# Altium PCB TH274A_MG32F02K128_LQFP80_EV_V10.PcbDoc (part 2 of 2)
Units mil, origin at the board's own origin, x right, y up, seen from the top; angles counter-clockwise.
Board outline 4251.97 x 2637.8 mil, 2 copper layers (Top Layer, Bottom Layer); 159 components, 159 nets, 691 pads, 305 vias.
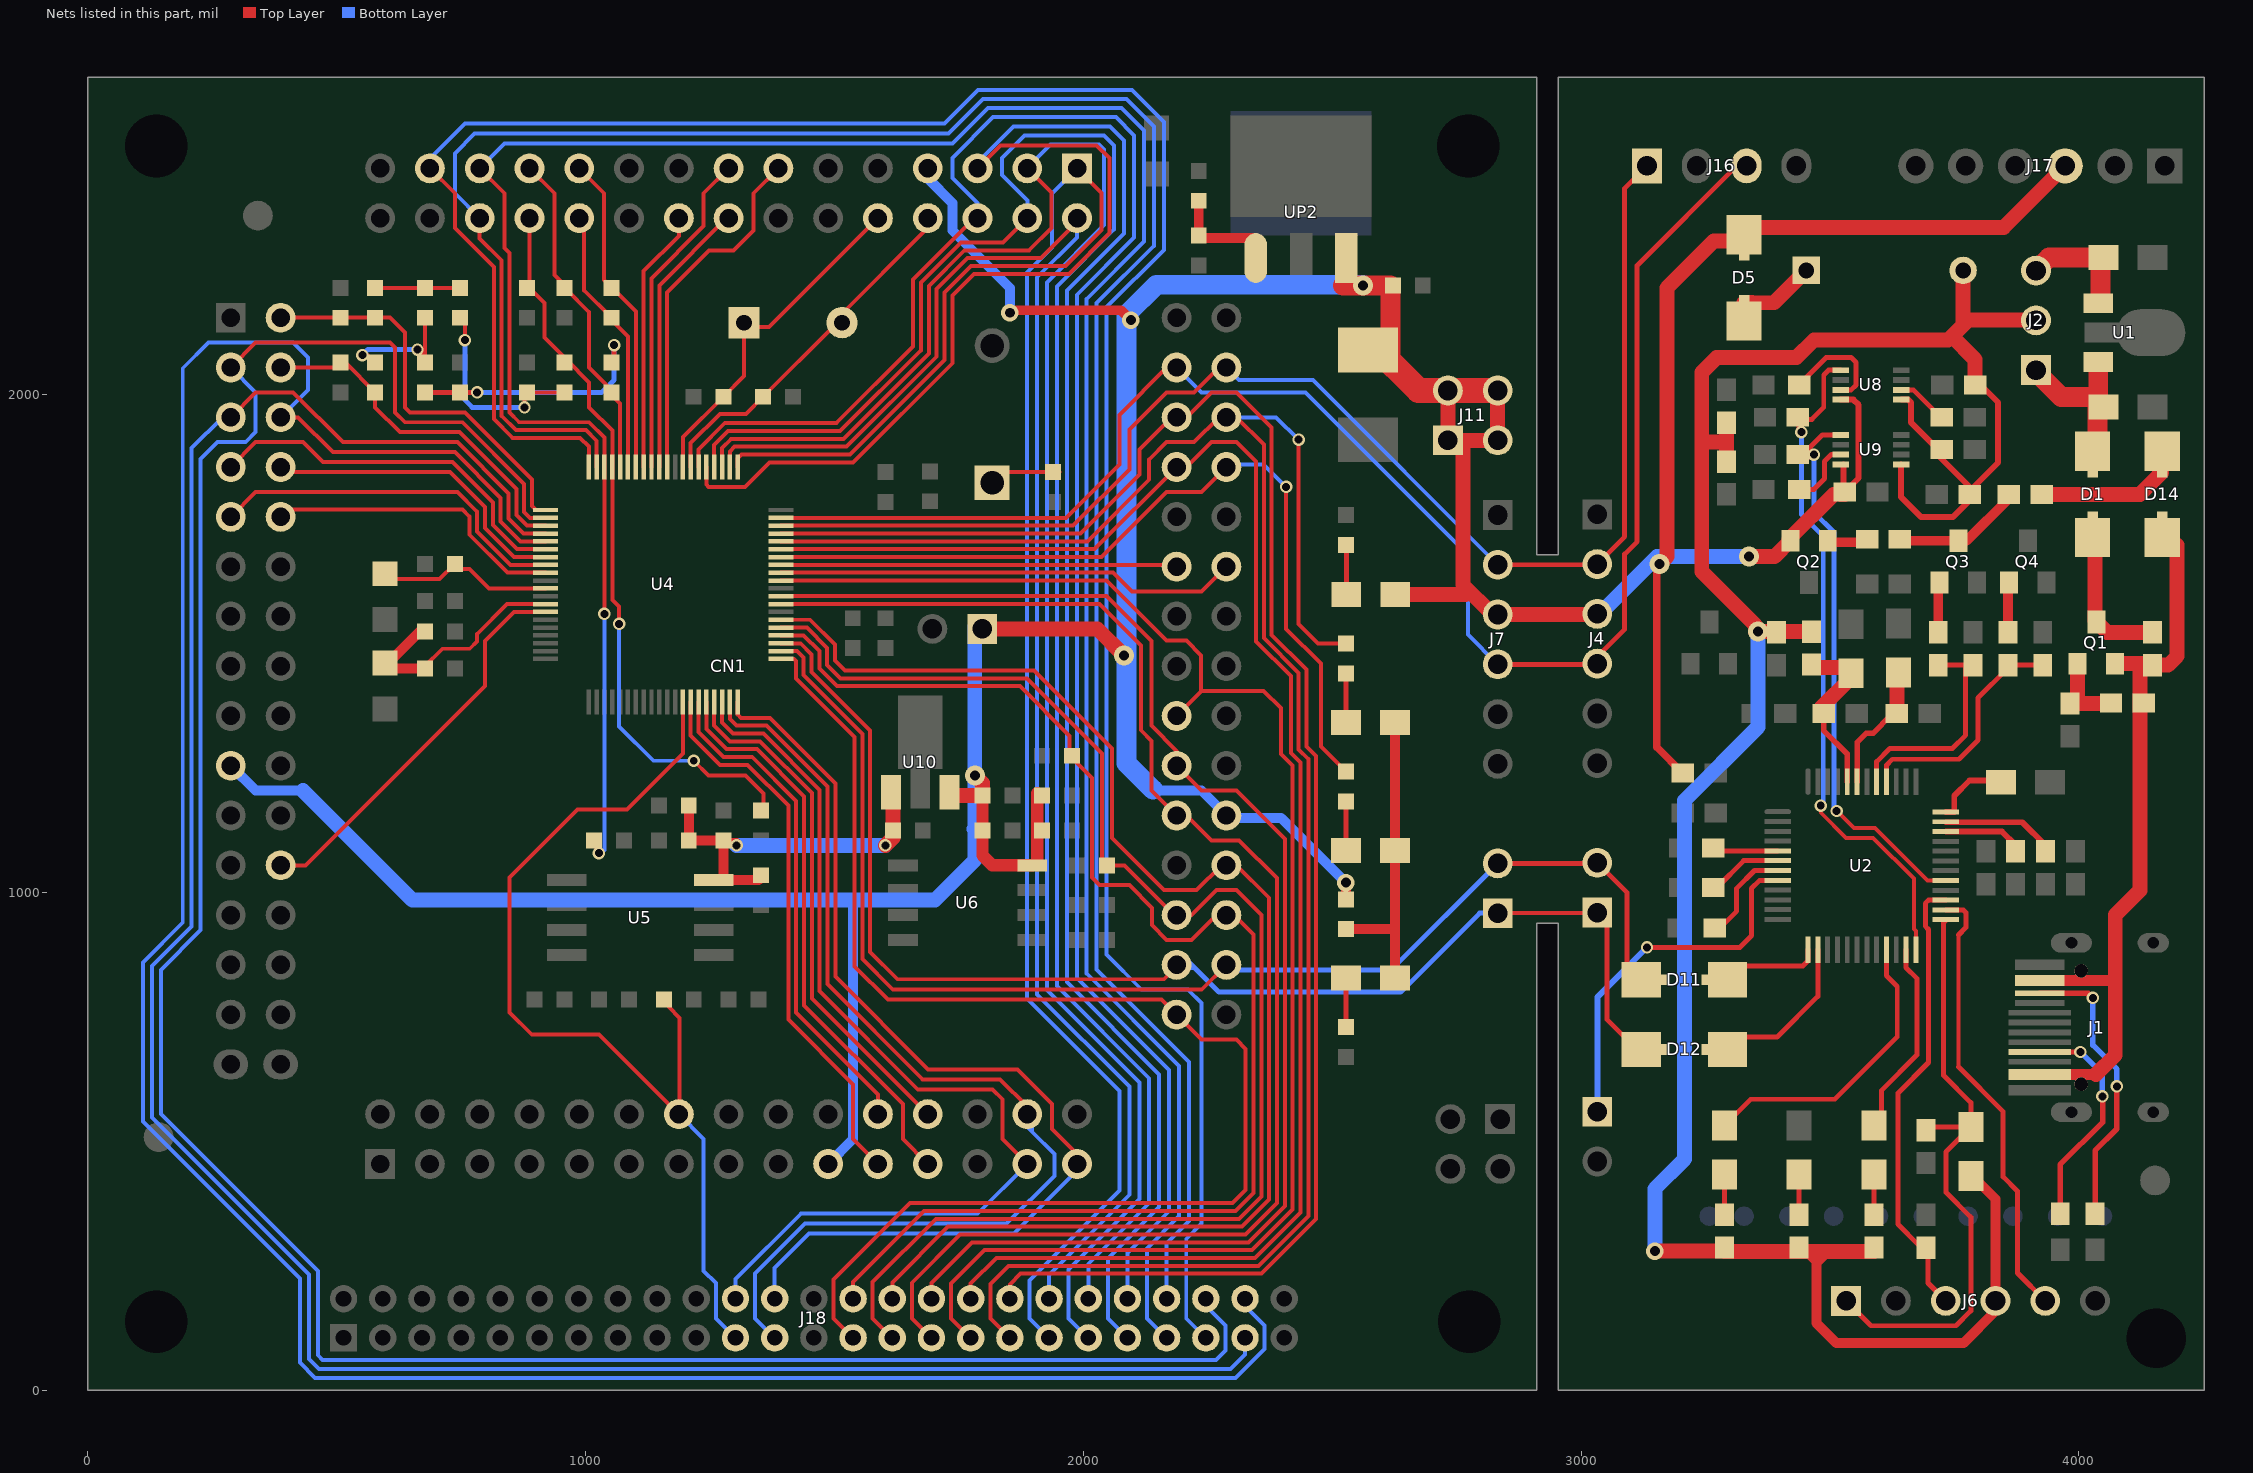
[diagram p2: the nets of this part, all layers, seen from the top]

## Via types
v1: diameter 20, hole 12, Top Layer to Bottom Layer, tented both sides, 214 vias
v2: diameter 25, hole 16, Top Layer to Bottom Layer, tented both sides, 55 vias
v3: diameter 30, hole 12, Top Layer to Bottom Layer, tented both sides, 13 vias
v4: diameter 40, hole 20, Top Layer to Bottom Layer, tented both sides, 7 vias
v5: diameter 25, hole 12, Top Layer to Bottom Layer, tented both sides, 6 vias
v6: diameter 35, hole 20, Top Layer to Bottom Layer, tented both sides, 6 vias
v7: diameter 30, hole 16, Top Layer to Bottom Layer, tented both sides, 2 vias
v8: diameter 15, hole 12, Top Layer to Bottom Layer, tented both sides, 1 vias
v9: diameter 28, hole 16, Top Layer to Bottom Layer, tented both sides, 1 vias

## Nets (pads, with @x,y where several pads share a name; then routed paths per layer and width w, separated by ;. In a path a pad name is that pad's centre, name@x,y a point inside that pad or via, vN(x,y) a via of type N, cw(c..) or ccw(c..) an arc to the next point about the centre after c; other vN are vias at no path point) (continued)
LCD_P18: CN1.14 J18.21 R50.1 U4.13 | length 1979.7
  Top Layer w8: R50.1@1167.48,785 1167.48,770 1189.12,748.36 CN1.14@1189.12,556.64 ; CN1.14@1184.2,558.28 1027.48,715 892.04,715 847.48,759.56 847.48,1030.71 984.03,1167.26 1083.44,1167.26 1195.59,1279.41 U4.13@1195.59,1382.91
  Bottom Layer w8: CN1.14@1187.48,555 1237.48,505 1237.48,240 1261.97,215.51 1261.97,145 J18.21@1301.34,105.63
LCD_P19: CN1.27 J18.22 U4.18 | length 2013.1
  Top Layer w8: U4.18@1274.33,1382.91 1274.33,1342.1 1296.67,1319.76 1357.26,1319.76 1470.47,1206.55 1470.47,802.01 1667.48,605 1817.48,605 1837.48,585 1837.48,505 CN1.27@1877.92,464.56
  Bottom Layer w8: J18.22@1301.34,184.37 1301.34,223.86 1432.48,355 1787.48,355 CN1.27@1887.48,455
LCD_P20: CN1.28 J18.23 U4.19 | length 2176.1
  Top Layer w8: U4.19@1290.08,1382.91 1290.08,1348.62 1303.19,1335.51 1363.78,1335.51 1486.22,1213.07 1486.22,816.26 1677.48,625 1832.48,625 1887.48,570 CN1.28@1887.48,555
  Bottom Layer w8: J18.23@1380.08,105.63 1340.71,145 1340.71,234.94 1440.76,335 1845.67,335 1941.93,431.26 1941.93,475 1897.48,519.45 ; CN1.28@1887.48,529.45 1897.48,519.45 ; CN1.28@1897.48,545 1897.48,519.45
LCD_P21: CN1.29 J18.24 U4.20 | length 2093.6
  Top Layer w8: U4.20@1305.83,1382.91 1305.83,1357.87 1312.44,1351.26 1370.3,1351.26 1501.97,1219.6 1501.97,831.22 1688.19,645 1867.99,645 1937.48,575.51 1937.48,525 CN1.29@1987.48,475 ; CN1.29@1987.48,454.29 CN1.29@1987.48,455
  Bottom Layer w8: J18.24@1380.08,184.37 1380.08,246.16 1448.91,315 1860.67,315 1987.48,441.81 CN1.29@1987.48,455
LCD_P22: CN1.32 J18.27 U4.21 | length 2867.9
  Top Layer w8: U4.21@1392.44,1469.53 1418.66,1469.53 1422.48,1465.71 1422.48,1430.46 1540.43,1312.51 1540.43,852.05 1607.48,785 2157.48,785 CN1.32@2187.48,755 2237.48,705 2307.48,705 2326.18,686.3 2326.18,402.88 2299.56,376.26 1651.93,376.26 1498.19,222.52 1498.19,145 J18.27@1537.56,105.63
LCD_P23: CN1.35 J18.28 R47.1 U4.24 | length 2862.9
  Top Layer w8: U4.24@1392.44,1516.77 1438.23,1516.77 1469.72,1485.28 1469.72,1450.48 1505.45,1414.76 1872.72,1414.76 1972.68,1314.8 R47.1@1972.68,1275 ; J18.28@1537.56,184.37 1537.56,218.23 1679.84,360.51 2306.08,360.51 2341.93,396.36 2341.93,916.3 2303.23,955 CN1.35@2287.48,955 2267.48,955 2217.48,905 2167.48,905 2137.89,934.59 2137.89,969.59 2092.48,1015 2032.48,1015 2017.48,1030 2017.48,1230.2 1975.08,1272.6 R47.1@1972.68,1275 ; R47.1@1972.68,1284.8 R47.1@1972.68,1275
LCD_P24: CN1.36 J18.29 R46.1 U4.25 | length 2938.9
  Top Layer w8: U4.25@1392.44,1532.52 1444.75,1532.52 1485.47,1491.8 1485.47,1457.01 1511.97,1430.51 1886.97,1430.51 2037.48,1280 2037.48,1055 R46.1@2047.48,1055 ; J18.29@1616.3,105.63 1576.93,145 1576.93,217.6 1704.09,344.76 2312.61,344.76 2357.68,389.83 2357.68,955.51 2308.19,1005 2267.48,1005 2217.48,955 CN1.36@2187.48,955 2182.48,955 2082.48,1055 R46.1@2052.48,1055
LCD_P25: CN1.37 J18.30 U4.26 | length 2842.7
  Top Layer w8: U4.26@1392.44,1548.27 1451.28,1548.27 1501.22,1498.32 1501.22,1466.26 1521.22,1446.26 1900.71,1446.26 2057.48,1289.49 2057.48,1110 2162.48,1005 2227.48,1005 2277.48,1055 CN1.37@2287.48,1055 2308.19,1055 2373.42,989.76 2373.42,383.31 2319.13,329.02 1728.35,329.02 1616.3,216.97 J18.30@1616.3,184.37
LCD_P26: CN1.40 J18.31 U4.28 | length 2962.2
  Top Layer w8: U4.28@1392.44,1579.76 2032.72,1579.76 2115.72,1496.76 2115.72,1326.25 2136.97,1305 2136.97,1205.51 CN1.40@2187.48,1155 2207.48,1155 2257.48,1105 2313.19,1105 2389.17,1029.02 2389.17,376.79 2325.65,313.27 1752.6,313.27 1655.67,216.34 1655.67,145 J18.31@1695.04,105.63
LCD_P27: CN1.42 J18.32 U4.29 | length 2874.7
  Top Layer w8: U4.29@1392.44,1595.51 2046.97,1595.51 2136.93,1505.55 2136.93,1335.55 2187.48,1285 CN1.42@2187.48,1255 2237.48,1205 2308.19,1205 2404.92,1108.27 2404.92,370.27 2332.17,297.52 1776.85,297.52 1695.04,215.71 J18.32@1695.04,184.37
LCD_P28: CN1.44 J18.33 U4.31 | length 3113.4
  Top Layer w8: U4.31@1392.44,1627.01 2046.18,1627.01 2166.93,1506.26 2206.93,1506.26 2236.93,1476.26 2236.93,1404.45 ; J18.33@1773.78,105.63 1734.41,145 1734.41,215.08 1801.1,281.77 2338.7,281.77 2420.67,363.74 2420.67,1255 2396.93,1278.74 2396.93,1370.55 2362.48,1405 2237.48,1405 2236.93,1404.45 ; CN1.44@2187.48,1355 2236.93,1404.45
LCD_P29: CN1.54 J18.34 U4.35 | length 3357.6
  Top Layer w8: U4.35@1392.44,1690 2022.48,1690 2184.98,1852.5 2187.48,1852.5 2189.98,1852.5 2192.48,1855 2207.48,1855 2257.48,1905 2308.19,1905 2346.93,1866.26 2346.93,1504.92 2416.93,1434.92 2416.93,1281.01 2436.42,1261.52 2436.42,357.22 2345.22,266.02 1825.35,266.02 1773.78,214.45 J18.34@1773.78,184.37
LCD_P30: CN1.55 J18.35 R55.1 U4.36 | length 4213.6
  Top Layer w8: U4.36@1392.44,1705.75 2008.23,1705.75 2132.48,1830 2132.48,1870 2167.48,1905 2222.48,1905 2272.48,1955 CN1.55@2287.48,1955 2308.19,1955 2362.68,1900.51 2362.68,1511.44 2432.68,1441.44 2432.68,1335 2432.68,1287.53 2452.17,1268.04 2452.17,350.7 2351.74,250.28 1849.61,250.28 1813.15,213.82 1813.15,145 J18.35@1852.52,105.63 ; v2(2432.48,1910) 2432.48,1539.49 2471.65,1500.32 R55.1@2527.52,1500.32 2485.94,1500.32
  Bottom Layer w8: CN1.55@2287.48,1955 2387.48,1955 v2(2432.48,1910)
LCD_P31: CN1.56 J18.36 U4.37 | length 3487.9
  Top Layer w8: U4.37@1392.44,1721.5 1993.98,1721.5 2112.48,1840 2112.48,1890 2177.48,1955 CN1.56@2187.48,1955 2207.28,1955 2257.28,2005 2308.19,2005 2378.42,1934.76 2378.42,1517.96 2448.42,1447.97 2448.42,1294.06 2467.91,1274.57 2467.91,344.17 2358.27,234.53 1873.86,234.53 1852.52,213.19 J18.36@1852.52,184.37
LCD_P32: CN1.61 J18.37 U4.41 | length 3720.9
  Top Layer w8: U4.41@1305.83,1855.35 1305.83,1872.16 1313.77,1880.1 1531.23,1880.1 1721.18,2070.05 1721.18,2205.97 1774.22,2259.02 1964.68,2259.02 2036.93,2331.26 2036.93,2405.55 CN1.61@1987.48,2455
  Bottom Layer w8: J18.37@1931.26,105.63 1891.89,145 1891.89,220.83 2072.48,401.42 2072.48,602.01 1886.93,787.56 1886.93,2246.26 1936.93,2296.26 1936.93,2404.45 CN1.61@1987.48,2455
LCD_P33: CN1.62 J18.38 U4.42 | length 3352.1
  Top Layer w8: U4.42@1290.08,1855.35 1290.08,1886.63 1299.3,1895.85 1524.71,1895.85 1705.43,2076.58 1705.43,2212.49 1767.7,2274.76 1915.43,2274.76 CN1.62@1991.57,2350.91
  Bottom Layer w8: J18.38@1931.26,184.37 1931.26,231.92 2092.48,393.14 2092.48,610.29 1906.93,795.85 1906.93,2236.26 1986.93,2316.26 CN1.62@1986.93,2355
LCD_P34: CN1.63 J18.39 U4.43 | length 3866.6
  Top Layer w8: U4.43@1274.33,1855.35 1274.33,1893.15 1292.78,1911.6 1518.18,1911.6 1689.68,2083.1 1689.68,2219.02 1761.18,2290.51 1891.18,2290.51 1935.93,2335.26 1935.93,2406.55 CN1.63@1887.48,2455
  Bottom Layer w8: CN1.63@1887.48,2456.74 1933.74,2503 2031.93,2503 2041.93,2493 2041.93,2340.97 1926.93,2225.97 1926.93,804.13 2112.48,618.58 2112.48,384.85 1970.63,243 1970.63,145 J18.39@2010,105.63
LCD_P35: CN1.64 J18.40 U4.44 | length 3840.9
  Top Layer w8: U4.44@1258.58,1855.35 1258.58,1899.67 1286.26,1927.35 1511.66,1927.35 1673.94,2089.62 1673.94,2225.54 1754.66,2306.26 1838.74,2306.26 CN1.64@1887.48,2355
  Bottom Layer w8: CN1.64@1887.48,2341.81 CN1.64@1887.48,2355 1887.48,2390.71 1836.93,2441.26 1836.93,2476.26 1881.93,2521.26 2041.93,2521.26 2061.93,2501.26 2061.93,2332.68 1946.93,2217.68 1946.93,812.41 2132.48,626.86 2132.48,376.57 2010,254.09 J18.40@2010,184.37
LCD_P36: CN1.65 J18.41 U4.45 | length 4586.3
  Top Layer w8: U4.45@1242.83,1855.35 1242.83,1819.65 1247.48,1815 1320.67,1815 1370.02,1864.36 1537.75,1864.36 1736.93,2063.53 1736.93,2199.45 1780.75,2243.27 1971.21,2243.27 2052.68,2324.74 2052.68,2475.55 2026.97,2501.26 1916.93,2501.26 ; CN1.65@1787.48,2455 1833.74,2501.26 1916.93,2501.26 ; 1851.93,2501.26 1916.93,2501.26
  Bottom Layer w8: CN1.65@1787.48,2455 1787.48,2466.81 1860.19,2539.52 2053.67,2539.52 2081.93,2511.26 2081.93,2324.4 1966.93,2209.4 1966.93,820.7 2152.48,635.15 2152.48,368.28 2049.37,265.17 2049.37,145 J18.41@2088.74,105.63
LCD_P37: CN1.66 J18.42 U4.46 | length 3918.9
  Top Layer w8: U4.46@1227.09,1855.35 1227.09,1890.45 1279.73,1943.1 1503.76,1943.1 1657.68,2097.01 1657.68,2231.55 1781.12,2355 CN1.66@1787.48,2355
  Bottom Layer w8: CN1.66@1787.48,2355 1787.48,2385 1736.93,2435.55 1736.93,2476.26 1818.45,2557.78 2065.41,2557.78 2101.93,2521.26 2101.93,2316.11 1986.93,2201.11 1986.93,828.98 2172.48,643.43 2172.48,360 2088.74,276.26 J18.42@2088.74,184.37
LCD_P38: CN1.85 J18.43 R53.1 U4.58 | length 5585.5
  Top Layer w8: CN1.85@787.48,2455 837.48,2405 837.48,2295 847.48,2285 847.48,1964.41 866.89,1945 1007.48,1945 1038.11,1914.37 U4.58@1038.11,1855.35 v2(1038.11,1560) ; v2@1021.97,1079.41 R53.1@1021.97,1104.41
  Bottom Layer w8: CN1.85@787.48,2455 837.48,2505 1737.48,2505 1808.52,2576.04 2077.15,2576.04 2121.93,2531.26 2121.93,2307.83 2006.93,2192.83 2006.93,837.27 2192.48,651.72 2192.48,350 2128.11,285.63 2128.11,145 J18.43@2167.48,105.63 ; v2@1031.97,1079.41 1038.11,1085.55 v2(1038.11,1560)
  other v2: 1026.97,1079.41
LCD_P39: CN1.86 J18.44 U4.59 | length 4930.7
  Top Layer w8: CN1.86@787.48,2355 787.48,2314.25 831.73,2270 831.73,1957.88 860.36,1929.25 1000.96,1929.25 1022.36,1907.85 U4.59@1022.36,1855.35
  Bottom Layer w8: CN1.86@787.48,2355 737.48,2405 737.48,2485 777.48,2525 947.48,2525 ; 817.48,2525 947.48,2525 ; J18.44@2167.48,184.37 2167.48,295 2212.48,340 2212.48,660 2026.93,845.55 2026.93,2184.54 2141.93,2299.54 2141.93,2539.54 2087.17,2594.3 1798.49,2594.3 1729.2,2525 947.48,2525
LCD_P40: CN1.87 J18.45 U4.60 | length 5071.3
  Top Layer w8: CN1.87@687.48,2455 737.48,2405 737.48,2335 815.98,2256.5 815.98,1951.36 853.84,1913.5 988.98,1913.5 1006.61,1895.87 U4.60@1006.61,1855.35
  Bottom Layer w8: CN1.87@687.48,2455 687.48,2475 757.48,2545 827.48,2545 ; 817.48,2545 827.48,2545 ; J18.45@2232.48,119.37 J18.45@2246.22,105.63 2206.85,145 2206.85,304.43 2237.42,335 2237.42,778 2210.42,805 2117.42,805 2046.93,875.49 2046.93,2176.26 2161.93,2291.26 2161.93,2548.61 2097.98,2612.56 1788.47,2612.56 1720.91,2545 827.48,2545
LCD_P41: CN1.93 J18.46 U4.62 | length 5097
  Top Layer w8: CN1.93@287.48,2055 337.48,2105 607.48,2105 617.48,2095 617.48,1965 637.48,1945 752.48,1945 876.73,1820.75 876.73,1764.99 888.73,1752.99 U4.62@920,1752.99
  Bottom Layer w8: CN1.93@287.48,2055 337.48,2005 337.48,1925 317.48,1905 260.67,1905 226.93,1871.26 226.93,924.96 146.93,844.96 146.93,555.55 462.48,240 462.48,70.71 471.93,61.26 2266.93,61.26 2285.59,79.92 2285.59,130.72 J18.46@2246.22,170.09
LCD_P42: CN1.95 J18.47 U4.64 | length 4832.2
  Top Layer w8: CN1.95@287.48,1955 337.48,2005 412.48,2005 512.48,1905 742.48,1905 845.24,1802.24 845.24,1751.94 875.68,1721.5 U4.64@920,1721.5
  Bottom Layer w8: CN1.95@287.48,1955 270.67,1955 208.93,1893.26 208.93,932.42 128.93,852.42 128.93,548.1 444.48,232.54 444.48,63.25 464.47,43.26 2295.87,43.26 2324.96,72.35 J18.47@2324.96,105.63
LCD_P43: CN1.96 J18.48 U4.65 | length 5330.8
  Top Layer w8: CN1.96@387.48,1955 422.48,1955 492.48,1885 737.48,1885 829.49,1792.99 829.49,1745.42 869.16,1705.75 U4.65@920,1705.75
  Bottom Layer w8: CN1.96@387.48,1955 442.48,2010 442.48,2075 412.48,2105 242.48,2105 190.93,2053.45 190.93,939.87 110.93,859.87 110.93,540.64 426.48,225.09 426.48,55.8 457.02,25.26 2306.16,25.26 2364.33,83.43 2364.33,130.72 J18.48@2324.96,170.09
LCD_V1: R80.1 R81.2 R100.2 | length 396.2
  Top Layer w8: v2(757.48,2110) R80.1@757.48,2150 ; v2(877.48,1975) R81.2@877.48,2000 ; R81.2@882.48,2005 R100.2@957.48,2005 R100.2@967.48,2005
  Bottom Layer w10: v2(757.48,2110) 757.48,1990 772.48,1975 v2(877.48,1975)
LCD_V2: R79.1 R80.2 R99.2 | length 180
  Top Layer w8: R99.2@577.48,2215 R79.1@677.48,2215 R80.2@747.48,2215 R80.2@757.48,2215
LCD_V3: R78.1 R79.2 R98.2 | length 258.2
  Top Layer w8: v2(551.89,2080) 562.48,2080 R98.2@577.48,2065 ; v2(662.48,2091) R78.1@677.48,2076 ; R78.1@677.48,2065 R78.1@677.48,2076 ; R79.2@677.48,2155 677.48,2091 R78.1@677.48,2076
  Bottom Layer w10: v2(551.89,2080) 562.89,2091 v2(662.48,2091)
LCD_VT: R33.1 R78.2 R97.2 | length 497.4
  Top Layer w10: R78.2@677.48,2005 R33.1@747.48,2005 v2(782.48,2005) ; R97.2@1052.48,2065 1057.48,2070 v2(1057.48,2100)
  Bottom Layer w10: v2(782.48,2005) 1032.48,2005 1057.48,2030 v2(1057.48,2100)
MG_PA0: CN1.114 U4.74 | length 796.3
  Top Layer w8: CN1.114@387.48,1055 437.55,1055 797.95,1415.4 797.95,1505.86 856.11,1564.02 U4.74@920,1564.02
MG_PB8(TX): CN1.33 D11.2 J5.2 J15.2 U4.22 | length 2596.8
  Top Layer w8: U4.22@1392.44,1485.28 1425.18,1485.28 1438.23,1472.23 1438.23,1436.98 1556.18,1319.03 1556.18,866.3 1617.48,805 2237.48,805 CN1.33@2287.48,855
  Top Layer w10: J15.2@2832.52,1058.74 J5.2@3032.52,1058.74 ; J5.2@3032.52,1060 3092.52,1000 3092.52,825 D11.2@3092.52,810
  Bottom Layer w10: CN1.33@2282.52,845 2287.48,845 2618.78,845 J15.2@2832.52,1058.74
MG_PB9(RX): CN1.34 D12.1 J5.1 J15.1 U4.23 | length 2593.9
  Top Layer w8: U4.23@1392.44,1501.02 1431.71,1501.02 1453.98,1478.75 1453.98,1443.5 1571.93,1325.55 1571.93,880.55 1626.41,826.07 2161.74,826.07 CN1.34@2187.48,851.81 ; J15.1@2832.52,958.74 J5.1@3032.52,958.74 ; J5.1@3032.52,960 J5.1@3038.29,954.23
  Top Layer w10: J5.1@3052.52,958 3052.52,745 D12.1@3105.91,691.61
  Bottom Layer w10: CN1.34@2202.48,850 2222.48,850 ; CN1.34@2212.48,860 2222.48,850 ; J15.1@2832.52,958.74 2796.22,958.74 2637.48,800 2272.48,800 2222.48,850
MG_PC0: CN1.53 R54.1 U4.34 | length 1729.8
  Top Layer w8: U4.34@1392.44,1674.25 2036.73,1674.25 2167.48,1805 2237.48,1805 CN1.53@2287.48,1855 ; v2(2407.48,1815) 2407.48,1530 2477.48,1460 2477.48,1293.5 R54.1@2527.52,1243.46
  Bottom Layer w8: CN1.53@2287.48,1860 2362.48,1860 v2(2407.48,1815)
MG_PD0: C66.1 CN1.81 U4.54 | length 646.7
  Top Layer w8: CN1.81@987.48,2455 1037.48,2405 1037.48,2231.22 1053.09,2215.61 1101.1,2167.6 U4.54@1101.1,1855.35
MG_PD1: C66.2 CN1.82 U4.55 | length 540.2
  Top Layer w8: CN1.82@987.48,2355 997.48,2345 997.48,2210 1049.98,2157.5 1049.98,2155 1049.98,2152.5 1085.35,2117.13 U4.55@1085.35,1855.35
MG_PD2: C62.1 CN1.83 R97.1 U4.56 | length 675.1
  Top Layer w8: CN1.83@887.48,2455 937.48,2405 937.48,2241 960.48,2218 960.48,2215 960.48,2213 1007.48,2166 1007.48,2055 1047.48,2015 1047.48,2005 1049.98,2002.5 1069.61,1982.87 U4.56@1069.61,1855.35
MG_PD3: C65.1 CN1.84 R51.1 R100.1 U4.57 | length 1528.9
  Top Layer w8: C65.1@884.98,2217.5 C65.1@887.48,2215 ; 887.48,2305 CN1.84@887.48,2355 C65.1@887.48,2215 ; v2(1067.48,1540) 1067.48,1574.49 1053.86,1588.11 U4.57@1053.86,1855.35 1053.86,1928.62 1007.48,1975 1007.48,2025 962.48,2070 917.48,2115 917.48,2185 C65.1@887.48,2215 ; v2(1217.48,1265) 1247.48,1235 1321.56,1235 1357.48,1199.08 R51.1@1357.48,1165
  Bottom Layer w8: v2(1067.48,1540) 1067.48,1334.2 1136.68,1265 v2(1217.48,1265)
MG_PD7: C64.1 CN1.92 R99.1 U4.61 | length 811.4
  Top Layer w8: CN1.92@387.48,2155 C64.1@507.48,2155 R99.1@577.48,2155 607.48,2155 637.48,2125 637.48,1975 647.48,1965 757.48,1965 892.48,1830 892.48,1776.97 900.71,1768.74 U4.61@920,1768.74
MG_PD9: C63.1 CN1.94 R98.1 U4.63 | length 726.8
  Top Layer w8: CN1.94@387.48,2055 507.48,2055 527.48,2055 ; C63.1@517.48,2065 R98.1@577.48,2005 577.48,1975 627.48,1925 747.33,1925 860.98,1811.34 860.98,1758.46 882.2,1737.24 U4.63@920,1737.24
MG_PD12: CN1.97 U4.66 | length 768.6
  Top Layer w8: CN1.97@287.48,1855 337.48,1905 432.48,1905 472.48,1865 732.48,1865 813.74,1783.74 813.74,1738.9 862.64,1690 U4.66@920,1690
MG_PD13: CN1.98 U4.67 | length 632.1
  Top Layer w8: CN1.98@387.48,1855 397.48,1845 727.48,1845 797.99,1774.49 797.99,1732.37 856.11,1674.25 U4.67@920,1674.25
MG_PD14: CN1.99 U4.68 | length 737
  Top Layer w8: CN1.99@287.48,1755 337.48,1805 742.48,1805 782.24,1765.24 782.24,1725.85 849.59,1658.5 U4.68@920,1658.5
MG_PD15: CN1.100 U4.69 | length 608.8
  Top Layer w8: CN1.100@387.48,1765 392.48,1770 752.48,1770 766.5,1755.98 766.5,1719.33 843.07,1642.76 U4.69@920,1642.76
MG_PE0: CN1.21 U4.14 | length 1116
  Top Layer w8: U4.14@1211.34,1382.91 1211.34,1316.01 1270.57,1256.77 1325.71,1256.77 1407.48,1175 1407.48,745 1537.44,615.04 1537.44,505.04 CN1.21@1587.48,455
MG_PE1: CN1.22 U4.15 | length 1011.1
  Top Layer w8: U4.15@1227.09,1382.91 1227.09,1322.53 1277.1,1272.52 1334.96,1272.52 1423.23,1184.25 1423.23,759.25 1587.48,595 CN1.22@1587.48,555
MG_PE2: CN1.23 U4.16 | length 1147.6
  Top Layer w8: U4.16@1242.83,1382.91 1242.83,1329.05 1283.62,1288.27 1344.21,1288.27 1438.98,1193.5 1438.98,773.5 1637.44,575.04 1637.44,505.04 CN1.23@1687.48,455
MG_PE3: CN1.24 U4.17 | length 1041.1
  Top Layer w8: U4.17@1258.58,1382.91 1258.58,1335.58 1290.14,1304.02 1350.74,1304.02 1454.72,1200.03 1454.72,787.76 CN1.24@1687.48,555
MG_PE8: CN1.49 U4.32 | length 931.4
  Top Layer w8: U4.32@1392.44,1642.76 2059.72,1642.76 2097.48,1605 2237.48,1605 CN1.49@2287.48,1655
MG_PE9: CN1.50 U4.33 | length 781.5
  Top Layer w8: U4.33@1392.44,1658.5 CN1.50@2173.98,1658.5
MG_PE12: CN1.73 U4.50 | length 720.9
  Top Layer w8: U4.50@1164.09,1855.35 1164.09,2205.61 1248.48,2290 1297.48,2290 1337.48,2330 1337.48,2405 CN1.73@1387.48,2455
MG_PE13: CN1.76 U4.51 | length 559.6
  Top Layer w8: U4.51@1148.35,1855.35 1148.35,2219.87 1283.48,2355 CN1.76@1287.48,2355
MG_PE14: CN1.75 U4.52 | length 663.8
  Top Layer w8: U4.52@1132.6,1855.35 1132.6,2234.12 1237.48,2339 1237.48,2405 CN1.75@1287.48,2455
MG_PE15: CN1.78 U4.53 | length 528.9
  Top Layer w8: U4.53@1116.85,1855.35 1116.85,2248.91 1187.48,2319.54 CN1.78@1187.48,2355
MG_VCAP: C60.1 C70.1 U4.71 | length 351.3
  Top Layer w8: C60.1@597.48,1630 706.84,1630 C70.1@737.48,1660.64 ; C70.1@737.48,1650 766.97,1650 805.71,1611.26 U4.71@920,1611.26
MG_VREF: C48.1 C71.1 R73.1 U4.73 | length 496.7
  Top Layer w8: R73.1@672.48,1515 672.48,1525 R73.1@672.48,1530 ; C71.1@677.48,1455 712.48,1490 767.48,1490 781.63,1504.15 781.63,1519.15 842.24,1579.76 U4.73@920,1579.76
  Top Layer w20: C48.1@602.48,1450.64 673.12,1450.64 675.3,1452.82 C71.1@677.48,1455 ; C48.1@602.48,1460 667.48,1525 672.48,1525 R73.1@677.48,1525
NetC2_2: C2.2 Q1.1 R5.2 | length 165
  Top Layer w30: R5.2@3982.52,1380 R5.2@3997.52,1380 ; Q1.1@3997.52,1460 R5.2@3997.52,1380 ; C2.2@4067.52,1380 4064.48,1380 R5.2@3997.52,1380
NetC6_1: C6.1 C7.2 R10.2 U2.44 | length 332.7
  Top Layer w11: C7.2@3487.48,1360 3487.48,1326 3534.71,1278.77 U2.44@3534.71,1223.13
  Top Layer w30: R10.2@3477.52,1452 3542.48,1452 C6.1@3542.48,1440.79 3542.48,1432 3481.48,1371 C7.2@3481.48,1366
NetC8_2: C8.2 C9.1 U2.43 | length 251
  Top Layer w11: U2.43@3554.4,1223.13 3554.4,1301.92 3572.48,1320 3586.48,1320 3622.98,1356.5 3634.48,1356.5 C8.2@3637.98,1356.5
  Top Layer w30: C8.2@3634.48,1360 C9.1@3634.48,1426.05
NetC11_1: C11.1 U2.36 | length 149.7
  Top Layer w12: U2.36@3732.98,1162.16 3749.68,1162.16 3749.68,1194.68 3780.38,1225.39 C11.1@3837.42,1225.39
NetD1_1: D1.1 Q1.3 R1.2 | length 276.4
  Top Layer w30: D1.1@4032.48,1698.39 4032.48,1546.98 Q1.3@4035.52,1543.94 4056.46,1523 R1.2@4147.52,1523
NetD2_1: D2.1 R6.2 | length 80.8
  Top Layer w10: R6.2@3288.07,353.26 D2.1@3288.07,434.05
NetD3_1: D3.1 R9.2 | length 80.8
  Top Layer w10: R9.2@3588.07,353.26 D3.1@3588.07,434.05
NetD4_1: D4.1 R11.2 | length 80.8
  Top Layer w10: R11.2@3438.07,353.26 D4.1@3438.07,434.05
NetD5_1: D5.1 SW1.1 | length 154.2
  Top Layer w30: D5.1@3327.48,2185.93 3343.41,2185.93 3342.48,2185 3387.52,2185 SW1.1@3452.52,2250
NetD8_1: D8.1 D9.1 D10.1 R58.1 | length 609.3
  Top Layer w20: R58.1@2527.52,926.61 2623.07,926.61 ; D10.1@2625.94,828.19 D8.1@2625.94,1085.04 D9.1@2625.94,1341.89
NetD8_2: D8.2 R54.2 | length 98.4
  Top Layer w10: D8.2@2527.52,1085.04 R54.2@2527.52,1183.46
NetD9_2: D9.2 R55.2 | length 98.4
  Top Layer w10: D9.2@2527.52,1341.89 R55.2@2527.52,1440.32
NetD10_2: D10.2 R56.2 | length 98.4
  Top Layer w10: R56.2@2527.52,729.76 D10.2@2527.52,828.19
NetD11_1: D11.1 U2.13 | length 188.6
  Top Layer w10: D11.1@3294.13,852.74 3445.52,852.74 3455.97,863.19 U2.13@3455.97,885.65
NetD12_2: D12.2 U2.14 | length 296
  Top Layer w10: D12.2@3307.52,709.74 3393.62,709.74 3475.66,791.78 U2.14@3475.66,885.65
NetD13_2: D13.2 R43.2 | length 100.3
  Top Layer w8: D13.2@2527.52,1599.53 D13.2@2528.31,1598.74
  Top Layer w10: D13.2@2528.31,1598.74 R43.2@2528.31,1697.95
NetD14_2: D14.2 R17.1 | length 272.5
  Top Layer w30: R17.1@3925.48,1800 4122.48,1800 D14.2@4166.56,1844.07 ; D14.2@4155.63,1868.15 D14.2@4167.48,1868.15 ; D14.2@4161.56,1844.07 D14.2@4162.48,1845
NetJ1_A5: J1.A5 R26.1 | length 460.3
  Top Layer w11: J1.A5@3921.32,679.9 v2(4003.07,679.9) ; R26.1@3962.52,354.74 3962.52,453.74 4047.52,538.74 v2@4047.52,590.74
  Bottom Layer w11: v2(4003.07,679.9) 4047.07,635.9 v2(4047.07,590.74)
NetJ1_B5: J1.B5 R27.2 | length 582.9
  Top Layer w11: J1.B5@3921.32,798.01 4018.8,798.01 v2(4028.07,788.74) ; R27.2@4032.52,354.74 4032.52,481.74 4076.52,525.74 v2(4076.52,610.74)
  Bottom Layer w11: v2(4028.07,788.74) 4028.07,693.74 4076.52,645.29 v2(4076.52,610.74)
NetQ2_1: Q2.1 R18.2 | length 72
  Top Layer w20: Q2.1@3495.48,1703.94 R18.2@3567.48,1703.94
NetQ3_1: Q3.1 R19.2 | length 97.5
  Top Layer w20: R19.2@3717.52,1523 Q3.1@3717.52,1620.53
NetQ3_2: Q3.2 R17.2 R18.1 | length 242.2
  Top Layer w20: R18.1@3660.51,1706.97 Q3.2@3758.02,1706.97 3774.45,1706.97 3859.48,1792 R17.2@3859.48,1800
NetQ4_1: Q4.1 R23.2 | length 97.5
  Top Layer w20: R23.2@3857.52,1523 Q4.1@3857.52,1620.53
NetR15_1: R15.1 U2.35 | length 263.6
  Top Layer w12: U2.35@3732.98,1141.47 3762.52,1141.47 ; 3794.78,1141.47 3762.52,1141.47 ; R15.1@3933.07,1083 3933.07,1095 3886.6,1141.47 3762.52,1141.47
NetR16_1: R16.1 U2.34 | length 163.6
  Top Layer w12: U2.34@3732.98,1122.79 3845.28,1122.79 3873.07,1095 R16.1@3873.07,1083
NetR29_2: R29.2 U8.7 | length 202.9
  Top Layer w10: R29.2@3452.48,2035 3492.48,2075 3542.48,2075 3552.48,2065 3552.48,2020 3542.64,2010.16 U8.7@3521.46,2010.16 U8.7@3519.34,2010.16
NetR30_2: R30.2 U9.7 | length 132.5
  Top Layer w10: R30.2@3438.48,1810 3467.48,1810 3488.98,1831.5 3488.98,1866.5 3502.64,1880.16 U9.7@3521.46,1880.16
NetR64_2: R64.2 U8.2 | length 108.2
  Top Layer w10: U8.2@3643.5,2010.16 3667.32,2010.16 R64.2@3723.48,1954 ; R64.2@3710.98,1968.5 R64.2@3714.48,1965
NetR94_2: R94.2 R95.1 UP2.1 | length 170
  Top Layer w20: R95.1@2231.97,2320 R94.2@2231.97,2375 ; R95.1@2236.97,2315 R95.1@2237.48,2315 ; R95.1@2237.48,2320 R95.1@2237.48,2315 ; UP2.1@2345.97,2315 R95.1@2237.48,2315 ; UP2.1@2346.48,2305 UP2.1@2347.48,2305
NetR96_2: R96.2 SW2.1 | length 134.4
  Top Layer w8: SW2.1@1817.48,1845 R96.2@1939.48,1845 R96.2@1951.93,1845
P44: J6.5 U2.26 | length 900.8
  Top Layer w8: 3758.07,650 3758.07,915
  Top Layer w10: U2.26@3732.98,965.31 3767.76,965.31 3773.07,960 3773.07,930 3758.07,915 ; 3758.07,650 3848.07,560 3848.07,429 3876.62,400.45 3876.62,235.9 J6.5@3932.52,180
P45: J6.3 R25.1 U2.27 | length 931.6
  Top Layer w10: R25.1@3696.8,290.72 3696.8,287 3696.8,215.72 J6.3@3732.52,180 ; R25.1@3698.07,292 3693.07,292 3678.51,292 3636.52,333.99 3636.52,597.19 3698.07,658.74 3698.07,926 3691.48,932.59 3691.48,978.41 3698.06,984.99 U2.27@3732.98,984.99 ; J6.3@3733.8,181.28 J6.3@3741.07,174
PA13_SWDIO: CN1.58 J4.4 J7.4 J16.3 U4.39 | length 3281.4
  Top Layer w8: U4.39@1392.44,1752.99 1965.47,1752.99 2072.48,1860 2072.48,1960 2167.48,2055 CN1.58@2187.48,2055
  Top Layer w10: J7.4@2832.52,1458.74 J4.4@3017.52,1458.74 ; J4.4@3025.52,1467 3087.52,1529 3087.52,1680 3112.52,1705 3112.52,2260.04 3312.48,2460 J16.3@3332.52,2460
  Bottom Layer w8: CN1.58@2187.48,2055 2237.48,2005 2446.26,2005 2772.52,1678.74 2772.52,1518.74 J7.4@2832.52,1458.74
PA14_SWCLK: CN1.57 J4.2 J7.2 J16.1 U4.38 | length 2824.1
  Top Layer w8: U4.38@1392.44,1737.24 1979.72,1737.24 2092.48,1850 2092.48,1930 2167.48,2005 2222.48,2005 2272.48,2055 CN1.57@2287.48,2055
  Top Layer w10: J7.2@2832.52,1658.74 J4.2@3032.52,1658.74 ; J4.2@3032.52,1660 3087.52,1715 3087.52,2415 J16.1@3132.52,2460
  Bottom Layer w8: CN1.57@2287.48,2055 2312.48,2030 2461.26,2030 J7.2@2832.52,1658.74
PASS: D3.2 U2.23 | length 394.2
  Top Layer w10: D3.2@3603.07,530 3603.07,532.47 3603.07,602.29 3674.52,673.74 3674.52,827.74 3652.82,849.44 U2.23@3652.82,885.65
RST: C12.2 J6.1 R22.2 U2.25 | length 1228.1
  Top Layer w10: J6.1@3532.52,180 3582.52,130 3753.07,130 3783.07,160 3783.07,348 3733.07,398 3733.07,479.21 C12.2@3783.07,529.21 ; R22.2@3699.28,529.21 C12.2@3783.07,529.21 ; U2.25@3733.07,945 3728.07,940 3728.07,633 3783.07,578 C12.2@3783.07,529.21 ; U2.25@3742.52,945.62 U2.25@3751.9,945.62
RST_CTRL_51: R19.1 R20.1 U2.41 | length 451.6
  Top Layer w10: U2.41@3593.77,1223.13 3593.77,1263.29 3620.48,1290 3746.22,1290 3772.52,1316.3 R20.1@3772.52,1457 ; R19.1@3717.52,1457 R20.1@3772.52,1457 ; R20.1@3787.52,1457 R20.1@3772.52,1457
RST_CTRL_ARM: R23.1 R24.1 U2.40 | length 474.1
  Top Layer w10: U2.40@3613.45,1223.13 3613.45,1256.14 3625.32,1268 3759.22,1268 3797.52,1306.3 3797.52,1391.3 R23.1@3854.98,1448.76 ; R23.1@3857.52,1457 R24.1@3927.52,1457
SWD_SCL_DIR: R63.2 U2.29 U9.5 | length 1149.4
  Top Layer w8: v2@3513.98,1164.5 3548.48,1130 3590.48,1130 3696.12,1024.36 U2.29@3732.98,1024.36
  Top Layer w10: R63.2@3446.48,1869 R63.2@3452.48,1875 ; R63.2@3447.48,1883 R63.2@3447.7,1882.64 ; R63.2@3449.95,1879.04 R63.2@3447.7,1882.64 ; R63.2@3450.41,1875 R63.2@3452.48,1875 ; v2@3469.41,1875 3467.48,1875 R63.2@3452.48,1875 ; U9.5@3521.46,1919.53 3484.59,1919.53 3456.27,1891.21 R63.2@3447.7,1882.64
  Bottom Layer w10: v2(3467.48,1880) 3467.48,1764.49 3508.48,1723.49 3508.48,1495 ; 3508.48,1505 3508.48,1495 ; v2@3518.48,1160 3513.98,1164.5 3508.48,1170 3508.48,1495
  other v2: 3513.48,1164
SWD_SDA_DIR: R62.2 U2.24 U8.5 | length 1381.2
  Top Layer w8: v2(3481.48,1175) 3481.48,1161 3532.48,1110 3586.48,1110 3668.48,1028 3668.48,927 3672.51,922.97 U2.24@3672.51,885.65
  Top Layer w10: v2@3437.48,1925 R62.2@3437.48,1951 ; R62.2@3439.48,1951 R62.2@3442.48,1951 ; R62.2@3442.48,1957 3442.48,1955 R62.2@3442.48,1951 ; U8.5@3521.46,2049.53 3497.01,2049.53 3487.48,2040 3487.48,1975 3463.48,1951 R62.2@3442.48,1951
  Bottom Layer w10: v2(3442.48,1925) 3442.48,1760 3486.48,1716 3486.48,1485 ; v2@3486.48,1175 3486.48,1485 ; 3486.48,1505 3486.48,1485
TOOL_OPTION0: R2.1 U2.5 | length 121.1
  Top Layer w10: R2.1@3275.52,1080 3279.44,1083.92 U2.5@3395,1083.92
TOOL_OPTION1: R3.1 U2.6 | length 142.8
  Top Layer w10: R3.1@3274.02,1011.54 3326.71,1064.23 U2.6@3395,1064.23
TOOL_OPTION2: R28.1 U2.7 | length 191.4
  Top Layer w10: R28.1@3278.52,928.74 3312.52,962.74 3312.52,1008.74 3348.33,1044.55 U2.7@3395,1044.55
USBOK: D2.2 U2.21 | length 605
  Top Layer w10: D2.2@3288.07,532.47 3340.6,585 3509.78,585 3635.15,710.37 3635.15,811.43 3613.45,833.13 U2.21@3613.45,885.65
VCC3: C67.1 C74.1 R32.2 R92.1 R93.1 U5.8 U10.1 | length 756.7
  Top Layer w20: R32.2@1207.48,1175 R93.1@1207.48,1105 C67.1@1277.48,1105 C67.1@1277.48,1100 ; U5.8@1257.48,1025 U5.8@1277.48,1025 ; C67.1@1276.48,1100 C67.1@1277.48,1100 ; v2@1303.64,1100 C67.1@1277.48,1100 ; R92.1@1357.48,1035 1354.98,1032.5 1347.48,1025 U5.8@1277.48,1025 ; U5.8@1277.48,1025 C67.1@1277.48,1100
  Top Layer w30: v2(1602.48,1095) 1617.48,1110 C74.1@1617.48,1125 U10.1@1617.48,1195.31
  Bottom Layer w30: v2(1303.64,1095) v2(1602.48,1095)
VCC_USB: C2.1 D14.1 J1.A4 J1.A9 J1.M5 J1.M6 Q1.2 R1.1 | length 1456.2
  Top Layer w22: J1.A4@3921.32,634.61 4004.72,634.61 4034.15,634.61 ; J1.A9@3921.32,823.62 4004.72,823.62 4073.07,823.62
  Top Layer w30: 4034.15,634.61 4073.07,673.54 4073.07,823.62 4073.07,955 4122.4,1004.33 4122.4,1381.26 4122.4,1446.88 ; Q1.2@4072.52,1460 4124.52,1460 ; R1.1@4137.52,1457 R1.1@4147.52,1457 4179.48,1457 4197.48,1475 D14.1@4197.48,1698.39
VCP_OPTION: J3.1 U2.8 | length 845.4
  Top Layer w10: v2(3132.48,890) 3157.52,890 ; 3257.52,890 3157.52,890 ; U2.8@3395,1024.86 3358.64,1024.86 3342.52,1008.74 3342.52,913.74 3318.78,890 3157.52,890
  Bottom Layer w12: J3.1@3032.52,560 3032.52,790.04 v2(3132.48,890)
VDD: C12.1 J2.2 J6.4 R4.1 R6.1 R9.1 R10.1 R11.1 R12.1 R13.1 R14.2 R40.2 R41.2 SW1.2 U8.1 U9.1 | length 5168.8
  Top Layer w12: R11.1@3447.26,279.52 3447.78,279 3473.07,253.71 3473.42,253.36 ; 3473.43,251.65 3499.59,277.81 ; U9.1@3642.48,1860.47 3642.48,1795 3682.48,1755 3747.48,1755 3780.48,1788 R40.2@3780.48,1800 ; U8.1@3643.5,1990.47 3657.01,1990.47 3662.48,1985 3662.48,1945 ; 3662.48,1955 3662.48,1945 ; R40.2@3780.48,1798 R40.2@3780.48,1800 ; R40.2@3780.48,1805 R40.2@3780.48,1800 ; R40.2@3780.48,1815 3714.98,1880.5 3714.48,1881 3714.48,1890 3714.48,1893 3662.48,1945 ; R4.1@3797.48,2025 3837.48,1985 3837.48,1863.83 3780.48,1806.83 R40.2@3780.48,1800
  Top Layer w20: 3473.07,279 3473.07,253.71 3473.07,135 3513.07,95 3768.07,95 3832.52,159.45 J6.4@3832.52,180 3832.52,384.55 3793.07,424 C12.1@3793.07,430.79
  Top Layer w30: v6(3148.07,280) R6.1@3288.07,280 ; 3242.48,1645 3350.47,1537.01 v4@3350.47,1525 ; 3242.48,1645.64 3242.48,1905 ; R6.1@3288.07,279 3438.07,279 3447.78,279 3473.07,279 R9.1@3588.07,279 ; R12.1@3292.48,1866 3292.48,1905 ; R13.1@3292.48,1944 3292.48,1905 ; v4@3364.73,1524.26 3392.48,1524.26 R10.1@3462.48,1524.26 ; 3767.48,2150 SW1.2@3767.48,2250 ; R4.1@3791.48,2020 3791.48,2071 3744.98,2117.5 ; J2.2@3913.9,2150 3777.48,2150 3744.98,2117.5 ; 3242.48,1905 3242.48,2045 3272.48,2075 3432.48,2075 3467.48,2110 3737.48,2110 3744.98,2117.5 ; 3242.48,1905 3292.48,1905
  Bottom Layer w30: v6(3148.07,280) 3148.07,405 3208.07,465 3208.07,1185.55 3355.47,1332.95 v4(3355.47,1525)
VDD3: C5.1 J2.3 U1.1 | length 238.5
  Top Layer w40: J2.3@3913.9,2249.69 3940.16,2275.94 C5.1@4043.86,2275.94 ; U1.1@4043.86,2184.06 C5.1@4043.86,2275.94 ; C5.1@4049.65,2275.94 C5.1@4043.86,2275.94
VDD5: C4.1 D1.2 J2.1 U1.3 | length 287.7
  Top Layer w40: J2.1@3912.42,2048.21 3964.68,1995.94 4038.86,1995.94 U1.3@4038.86,2065.94 ; D1.2@4037.48,1901.61 C4.1@4037.48,1971.26
VDUT: C17.1 C73.1 C75.1 C76.1 CN1.19 CN1.39 CN1.67 CN1.109 D5.2 D13.1 J4.3 J7.3 J11.1 J11.2 J11.3 J11.4 J17.3 JP3.1 Q2.2 R7.1 R44.2 R45.2 R58.2 TC2.1 U6.8 U8.8 U9.8 U10.3 UP2.3 | length 10320.2
  Top Layer w12: U8.8@3521.46,1990.47 3547.01,1990.47 3557.48,1980 3557.48,1833 C17.1@3529.48,1805 ; U9.8@3527.48,1860.47 3527.48,1805 C17.1@3528.48,1804
  Top Layer w15: v4@3152.48,1660.64 3152.48,1660 3152.48,1292 R7.1@3204.48,1240
  Top Layer w20: v6@1852.48,2170 2075.67,2170 v6(2095.67,2150) ; R58.2@2527.52,986.61 v6(2527.52,1020)
  Top Layer w25: C75.1@1797.48,1185 C73.1@1797.48,1125 1797.48,1075 1817.48,1055 ; 1807.48,1065 1817.48,1055 ; U6.8@1897.48,1055 1817.48,1055 ; U6.8@1907.48,1055 1907.48,1125 1907.48,1195 R45.2@1907.48,1200
  Top Layer w30: U10.3@1727.48,1195 1731.5,1195 C75.1@1797.48,1195 1797.48,1220 v4(1782.48,1235) ; JP3.1@1816.93,1530 2028.19,1530 v4(2081.93,1476.26) ; D13.1@2626.73,1598.74 2767.52,1598.74 ; J11.1@2732.52,1908.74 J11.2@2732.52,2008.74 ; J7.3@2832.52,1548.74 2827.52,1553.74 J7.3@2822.52,1558.74 ; J11.4@2832.52,2008.74 J11.3@2832.52,1908.74 2762.52,1908.74 2762.52,1618.74 J7.3@2822.52,1558.74 ; J4.3@3032.52,1558.74 J7.3@2832.52,1558.74 J7.3@2822.52,1558.74 ; v4@3157.45,1660.03 3172.48,1675.06 3172.48,2215 3266.54,2309.06 3326.57,2309.06 3333.31,2315.79 3354.13,2336.61 3849.13,2336.61 J17.3@3972.52,2460 ; v4(3337.48,1675) 3388.51,1675 Q2.2@3420.48,1706.97 ; Q2.2@3417.46,1709.98 C17.1@3507.48,1800 ; C17.1@3522.48,1800 C17.1@3529.48,1800
  Top Layer w40: 2521.97,2220 2528.48,2220 v4(2561.97,2220) C76.1@2617.52,2220 ; TC2.1@2617.52,2075 2617.52,2090 C76.1@2617.52,2205
  Top Layer w50: TC2.1@2577.48,2105 2582.22,2100.26 2673.74,2008.74 J11.2@2732.52,2008.74 J11.4@2832.52,2008.74
  Bottom Layer w20: CN1.109@287.48,1255 337.48,1205 432.48,1205 ; CN1.19@1487.48,455 1537.48,505 1537.48,985 ; CN1.67@1687.48,2455 1687.48,2435 1737.48,2385 1737.48,2330 1852.48,2215 v6@1852.48,2170 ; 2137.48,1205 2237.48,1205 CN1.39@2287.48,1155 ; CN1.39@2287.48,1150 2397.52,1150 v6(2527.52,1020)
  Bottom Layer w30: 432.48,1205 652.48,985 1537.48,985 1701.84,985 1781.93,1065.09 1781.93,1126.26 ; 1780.33,1127.85 1781.93,1129.45 1781.93,1235 1781.93,1530 JP3.1@1781.93,1535 ; J4.3@3034.37,1556.89 3035,1557.52 3147.48,1670 3152.48,1675 3157.48,1675 v4(3337.48,1675)
  Bottom Layer w40: 2139.7,1207.22 2086.93,1260 2086.93,1476.26 2086.93,2150 2086.93,2161.26 2146.93,2221.26 v4@2561.97,2221.26
  other v4: 3157.48,1660
  other v6: 1852.48,2165
XIN/MG_PC13: C19.1 CN1.68 U4.47 X1.2 | length 734.6
  Top Layer w8: U4.47@1211.34,1855.35 1211.34,1902.94 1270.41,1962.01 1322.68,1962.01 C19.1@1356.93,1996.26 1496.93,2136.26 1496.93,2144.45 1506.42,2153.94 1687.48,2335 CN1.68@1687.48,2355 ; C19.1@1356.93,1986.26 C19.1@1361.93,1991.26
XOUT/MG_PC14: C59.1 CN1.70 U4.48 X1.1 | length 691.4
  Top Layer w8: U4.48@1195.59,1855.35 1195.59,1914.92 C59.1@1276.93,1996.26 1318.5,2037.83 1318.5,2136.26 1368.74,2136.26 CN1.70@1587.48,2355
pads on no net: CN1.1 CN1.15 CN1.16 CN1.18 CN1.20 CN1.25 CN1.26 CN1.30 CN1.31 CN1.38 CN1.43 CN1.45 CN1.46 CN1.47 CN1.48 CN1.51 CN1.52 CN1.60 CN1.71 CN1.72 CN1.74 CN1.77 CN1.79 CN1.80 CN1.88 CN1.89 CN1.90 CN1.91 CN1.101 CN1.102 CN1.103 CN1.104 CN1.105 CN1.106 CN1.108 CN1.110 CN1.111 CN1.112 CN1.113 CN1.121 CN1.122 J1.A8 J1.B8 J6.6 J7.1 U2.1 U2.2 U2.3 U2.4 U2.28 U2.30 U2.32 U2.37 U2.38 U2.39 U2.46 U8.3 U8.6 U9.3 U9.6

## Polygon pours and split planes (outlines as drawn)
GND on Top Layer "Top Layer-No Net" (hatched 90Degree grid 10 track 10, remove dead copper, pour order 1001): 27.56,20 4227.48,20 4227.48,2610 27.56,2610
GND on Bottom Layer "Top Layer-No Net" (hatched 90Degree grid 10 track 10, remove dead copper, pour order 1001): 27.56,20 4227.48,20 4227.48,2610 27.56,2610

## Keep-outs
Top Layer:
  circle w5: c4153.07,421.9 r59.06
  circle w5: c142.56,509 r59.06
  circle w5: c341.97,2360 r59.06
Keep-Out Layer:
  circle w7.88: c137.8,137.8 r118.11
  circle w7.88: c2775.59,137.8 r118.11
  circle w7.88: c2773.07,2500 r118.11
  circle w7.88: c137.8,2500 r118.11
  lines w15: 0,0 0,2637.8 2910.87,2637.8 2910.87,1678.74 2954.17,1678.74 ; 2910.87,0 2910.87,938.74 2954.17,938.74 ; 4251.97,1.26 4251.97,2639.06 4251.97,1.26

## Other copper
Top Layer:
  pour cut-out: 2867.48,2623.74 2987.48,2623.74 2987.48,0 2867.48,0
Bottom Layer:
  pour cut-out: 2867.48,2625 2987.48,2625 2987.48,0 2867.48,0

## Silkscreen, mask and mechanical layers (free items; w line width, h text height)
Top Overlay:
  circle w10: c137.8,137.8 r137.8
  circle w4: c2775.59,137.8 r137.8
  circle w10: c2773.07,2500 r137.8
  circle w10: c137.8,2500 r137.8
  region: 3161.92,1068.04 3115.02,1093.69 3116.92,1078.04 3087.52,1078.04 3087.52,1058.04 3116.92,1058.04 3115.02,1043.69
  region: 3088.47,955.86 3135.37,930.21 3133.47,945.86 3162.52,945.86 3162.52,965.86 3133.47,965.86 3135.37,980.21
  region: 3034.59,264.05 3060.25,335.95 3044.59,334.05 3044.59,394.05 3024.59,394.05 3024.59,334.05 3010.25,335.95
  region: 592.28,235.63 618.13,271.9 602.48,270 602.48,320 582.48,320 582.48,270 568.13,271.9
  region: 2771.88,1059.29 2724.98,1084.94 2726.88,1069.29 2676.88,1069.29 2676.88,1049.29 2726.88,1049.29 2724.98,1034.94
  region: 2678.43,947.11 2725.34,921.46 2723.43,937.11 2773.43,937.11 2773.43,957.11 2723.43,957.11 2725.34,971.46
  lines w6: 482.48,2229.67 482.48,1955.64 567.48,1870.64 567.48,1795 907.48,1795 1016.72,1904.24 1121.84,1904.24 1121.84,2304.36 ; 482.48,2290.64 482.48,2305 547.42,2305
  lines w15: 317.09,-36.22 317.09,282.8 386.97,282.8 ; 2637.56,282.8 2679.29,282.8 2679.29,-35
  text "System Power" at 2217.42,2585 h45
  text "When J16 Open" at 2977.48,2580 h45
  text "SW1 must be off" at 2977.48,2520.64 h45
  text "PD6" at 702.48,2515 h30 r90
  text "PD4" at 802.48,2515 h30 r90
  text "PD2" at 902.48,2515 h30 r90
  text "PD0" at 1002.48,2515 h30 r90
  text "PE14" at 1302.48,2515 h30 r90
  text "PE12" at 1402.48,2515 h30 r90
  text "GND" at 1602.52,2515 h30 r90
  text "VDUT" at 1702.52,2515 h30 r90
  text "PC11" at 1802.48,2515 h30 r90
  text "PC9" at 1902.48,2515 h30 r90
  text "PC7" at 1961.97,2515 h30 r90
  text "RST" at 3577.42,2415 h37 r90
  text "GND" at 3627.42,2415 h37 r90
  text "Power" at 3542.48,2350 h45
  text "Off" at 3408.38,2348.32 h45
  text "On" at 3762.48,2345 h45
  text "5V" at 2607.42,2335 h45
  text "SCL" at 4087.48,2325 h35 r90
  text "CLK" at 4192.48,2325 h35 r90
  text "SDA" at 3897.42,2320 h37 r90
  text "VCC" at 3987.48,2320 h37 r90
  text "PD3" at 842.48,2265 h30
  text "PD1" at 957.48,2265 h30
  text "PE13" at 1240.94,2260.51 h30
  text "PC14" at 1541.97,2260 h30
  text "PD5" at 811.97,2213.97 h30 r90
  text "PC8" at 2001.97,2210 h30 r90
  text "VDD3" at 3852.48,2195 h37 r90
  text "PC13" at 1697.48,2185 h30 r90
  text "PC12" at 1761.97,2185 h30 r90
  text "PC10" at 1901.97,2185 h30 r90
  text "PE15" at 1196.97,2183.97 h30 r90
  text "PD7" at 476.97,2160 h30 r90
  text "PC6" at 2352.48,2136 h30
  text "VDD" at 3762.48,2115 h37
  text "VDUT" at 2716.97,2070 h35
  text "VDD5" at 3732.48,2060 h37
  text "PC4" at 2352.48,2036 h30
  text "PD8" at 137.48,2035 h30
  text "PC5" at 2037.48,2035 h30
  text "PD9" at 476.97,2030 h30 r90
  text "PC3" at 2037.48,1940 h30
  text "PC2" at 2352.48,1936 h30
  text "PD10" at 111.97,1935 h30
  text "RESET" at 1731.97,1905 h30 r90
  text "PD11" at 476.97,1895 h30 r90
  text "LCD Cap. Ext." at 622.48,1870 h40
  text "PD13" at 451.46,1840 h30
  text "PC1" at 2037.48,1840 h30
  text "PC0" at 2352.48,1836 h30
  text "PD12" at 111.97,1835 h30
  text "R-Ladder" at 622.48,1810 h40
  text "PD15" at 451.46,1740 h30
  text "PD14" at 111.97,1735 h30
  text "Power" at 2566.97,1705 h35
  text "SCL" at 2691.97,1645 h33
  text "PE9" at 2037.48,1640 h30
  text "PE8" at 2352.48,1640 h30
  text "VDUT" at 2661.97,1515 h33
  text "SDA" at 2686.97,1440 h33
  text "LDO-3.3V" at 1542.48,1410.64 h40
  text "GND" at 2686.97,1340 h33
  text "GND" at 137.48,1335 h30
  text "PB15" at 2022.48,1335 h30
  text "VDUT" at 106.97,1240 h30
  text "RST" at 2691.97,1240 h33
  text "GND" at 2347.52,1238.74 h30
  text "PB14" at 2022.48,1235 h30
  text "VDUT" at 2347.52,1138.74 h30
  text "PB13" at 2017.48,1135 h30
  text "PB8_TX" at 2692.52,1128.74 h38
  text "PB12" at 2352.52,1043.74 h30
  text "PA0" at 451.97,1035 h30
  text "PB10" at 2352.52,943.74 h30
  text "PA1" at 126.97,935 h30
  text "PA2" at 451.97,935 h30
  text "PB11" at 2122.48,910 h30 r90
  text "SPI Flash" at 647.48,880 h45
  text "PB8" at 2352.52,843.74 h30
  text "PA3" at 126.97,840 h30
  text "PB9_RX" at 2691.97,840 h38
  text "PA4" at 451.97,835 h30
  text "PB9" at 2042.48,826.07 h30
  text "I2C EEPROM" at 1527.48,815 h45
  text "PB7" at 2042.52,743.74 h30
  text "PA6" at 451.97,740 h30
  text "PA5" at 126.97,730 h30
  text "PA7" at 612.52,618 h30 r90
  text "PA9" at 702.52,618 h30 r90
  text "PA11" at 802.52,618 h30 r90
  text "PA13" at 902.52,618 h30 r90
  text "PA15" at 1002.52,618 h30 r90
  text "PB1" at 1107.52,618 h30 r90
  text "PB3" at 1207.52,618 h30 r90
  text "PE1" at 1602.52,618 h30 r90
  text "PE3" at 1702.52,618 h30 r90
  text "PB5" at 1902.52,618 h30 r90
  text "TH274A" at 2077.56,580 h60
  text "2025.02" at 2467.56,580 h35
  text "MG32F02K128" at 2087.56,490.64 h50
  text "LQFP80_EV_V10" at 2087.56,400 h50
  text "GND" at 2767.56,340.64 h35
  text "LCD_P1" at 457.42,325 h30
  text "PE0" at 1606.97,310 h30 r90
  text "PE2" at 1706.97,310 h30 r90
  text "PB4" at 1907.52,310 h30 r90
  text "PB6" at 2007.52,310 h30 r90
  text "GND" at 1406.97,305 h30 r90
  text "PA8" at 702.52,301.54 h30 r90
  text "PB0" at 1107.52,301.54 h30 r90
  text "PB2" at 1207.52,301.54 h30 r90
  text "STN LCD Module IF" at 2137.56,290 h39.37
  text "PA10" at 801.97,280 h30 r90
  text "PA12" at 901.97,280 h30 r90
  text "PA14" at 1001.97,280 h30 r90
  text "VDUT" at 1506.97,280 h30 r90
  text "+VDD" at 411.04,240.53 h35
  text "3" at 662.48,235 h30
  text "5" at 741.22,235 h30
  text "7" at 819.96,235 h30
  text "9" at 898.7,235 h30
  text "11" at 972.48,235 h30
  text "13" at 1047.48,235 h30
  text "15" at 1126.22,235 h30
  text "17" at 1204.96,235 h30
  text "19" at 1283.7,235 h30
  text "21" at 1362.44,235 h30
  text "G" at 1451.18,235 h30
  text "23" at 1509.92,235 h30
  text "25" at 1588.66,235 h30
  text "27" at 1667.4,235 h30
  text "29" at 1746.14,235 h30
  text "31" at 1824.88,235 h30
  text "33" at 1903.62,235 h30
  text "35" at 1982.36,235 h30
  text "37" at 2061.1,235 h30
  text "39" at 2139.84,235 h30
  text "41" at 2218.58,235 h30
  text "43" at 2297.32,235 h30
  text "GND" at 2382.48,235 h30
  text "J3" at 2992.52,201.9 h45
  text "Open Disable VCP." at 2973.07,130 h40
  text "Open Disable VCP." at 2973.07,130 h40
  text "Short Enable VCP." at 2973.07,35 h40
  text "Short Enable VCP." at 2973.07,35 h40
  text "LCD_P0" at 442.48,20 h30
  text "2" at 661.22,20 h30
  text "4" at 739.96,20 h30
  text "6" at 818.7,20 h30
  text "8" at 897.44,20 h30
  text "10" at 967.48,20 h30
  text "12" at 1047.48,20 h30
  text "14" at 1126.22,20 h30
  text "16" at 1204.96,20 h30
  text "18" at 1283.7,20 h30
  text "20" at 1362.44,20 h30
  text "G" at 1451.18,20 h30
  text "22" at 1509.92,20 h30
  text "24" at 1588.66,20 h30
  text "26" at 1667.4,20 h30
  text "28" at 1746.14,20 h30
  text "30" at 1824.88,20 h30
  text "32" at 1903.62,20 h30
  text "34" at 1982.36,20 h30
  text "36" at 2061.1,20 h30
  text "38" at 2139.84,20 h30
  text "40" at 2218.58,20 h30
  text "42" at 2297.32,20 h30
  text "GND" at 2376.26,20 h30
Mechanical 1:
  circle w7.88: c2932.52,1613.74 r27
  circle w7.88: c2932.52,1503.74 r27
  circle w7.88: c2932.52,1416.74 r25
  circle w7.88: c2932.52,1298.74 r25
  circle w7.88: c2932.52,1008.74 r33
  lines w7.88: 2910.87,1078.74 2910.87,1232.74 2954.17,1232.74 2954.17,1078.74 2910.87,1078.74
  lines w11.81: 0,0 0,2637.8 2910.87,2637.8 2910.87,1678.74 2954.17,1678.74 2954.17,2637.8 4251.97,2637.8 4251.97,0 2954.17,0 2954.17,938.74 2910.87,938.74 2910.87,0 0,0
Mechanical 2:
  lines w6: 2932.52,1031.74 2932.52,1008.74 2955.52,1008.74 ; 2932.52,1321.74 2932.52,1298.74 2955.52,1298.74 ; 2932.52,1441.74 2932.52,1418.74 2955.52,1418.74 ; 2932.52,1526.74 2932.52,1503.74 2955.52,1503.74 ; 2932.52,1636.74 2932.52,1613.74 2955.52,1613.74

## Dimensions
0,0 to 0,2637.8 on Top Overlay
0,0 to 4251.97,0 on Top Overlay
